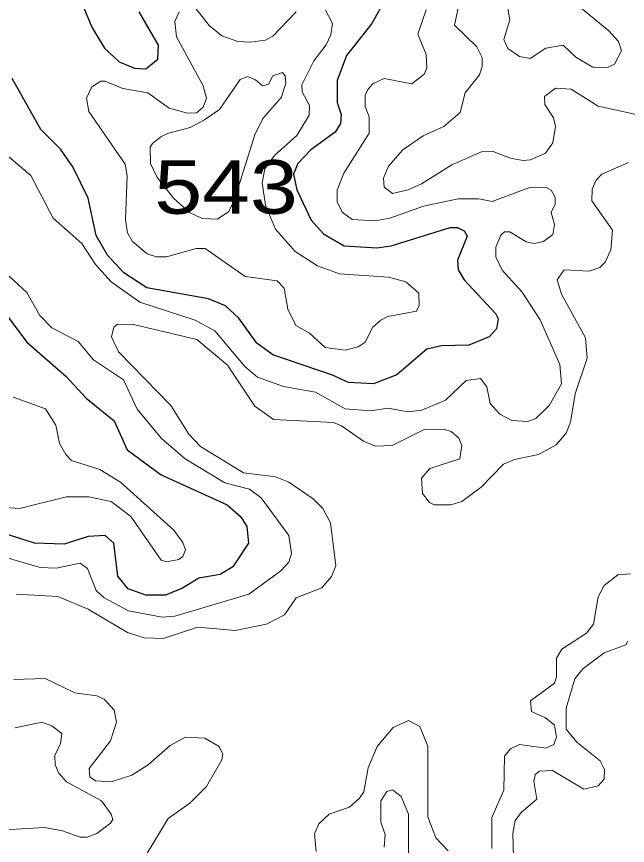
# Model space of a CAD drawing. Extents: x 577 to 602.9, y 7483.8 to 7511.6.
# Drawn here: x 585.493 to 586.406, y 7497.028 to 7498.265 of the extents above; entities that cross this region are included whole.
import ezdxf
from ezdxf.enums import TextEntityAlignment as Align

# ---------------------------------------------------------------- set-up
doc = ezdxf.new("R2010")
doc.units = 0
doc.header["$LTSCALE"] = 0.032
doc.layers.add('1', color=7, linetype='Continuous', lineweight=25)
doc.layers.add('2', color=7, linetype='Continuous', lineweight=13)
doc.layers.add('61', color=7, linetype='Continuous')

msp = doc.modelspace()

# ---------------------------------------------------------------- linework, layer by layer
at = {"layer": '1'}
for points in [[(585.5778, 7498.3164), (585.6057, 7498.2488), (585.6247, 7498.2178), (585.6462, 7498.1971), (585.6693, 7498.1876), (585.686, 7498.1868), (585.7043, 7498.2011), (585.705, 7498.2218), (585.6764, 7498.2719)], [(586.0509, 7498.3029), (586.0239, 7498.2544), (585.9857, 7498.2067), (585.9722, 7498.1693), (585.9722, 7498.1367), (585.9778, 7498.1184), (585.977, 7498.1049), (585.969, 7498.0921), (585.9325, 7498.0659), (585.9134, 7498.0452), (585.907, 7498.0293), (585.9118, 7498.0063), (585.9333, 7497.9609), (585.9516, 7497.9403), (585.9826, 7497.9228), (586.0311, 7497.9196), (586.0525, 7497.9228), (586.1408, 7497.9498), (586.1519, 7497.9498), (586.1615, 7497.945), (586.1662, 7497.9371), (586.1519, 7497.9013), (586.1527, 7497.887), (586.1615, 7497.8719)], [(586.1615, 7497.8719), (586.2084, 7497.8218), (586.2124, 7497.8138), (586.21, 7497.7987), (586.1989, 7497.7868), (586.1686, 7497.7741), (586.1281, 7497.7733), (586.1058, 7497.7685), (586.0613, 7497.7303), (586.0263, 7497.7168), (585.9889, 7497.7184), (585.9651, 7497.7295), (585.876, 7497.7598), (585.8522, 7497.7773), (585.8251, 7497.8146), (585.8052, 7497.8329), (585.7798, 7497.8433), (585.6876, 7497.86), (585.6534, 7497.8822), (585.6287, 7497.9085), (585.612, 7497.9379), (585.6001, 7497.9935), (585.577, 7498.0405), (585.5587, 7498.0667), (585.5293, 7498.0961), (585.4864, 7498.1725)], [(585.4673, 7497.8337), (585.5086, 7497.7788), (585.5667, 7497.728), (585.5969, 7497.6954), (585.639, 7497.6612), (585.6581, 7497.6182), (585.709, 7497.5808), (585.8076, 7497.5363), (585.8283, 7497.518), (585.837, 7497.5037), (585.8394, 7497.4791), (585.8164, 7497.4433), (585.7973, 7497.4321), (585.7655, 7497.4266), (585.7408, 7497.4115), (585.7154, 7497.4011), (585.686, 7497.4011), (585.6597, 7497.4107), (585.6446, 7497.4298), (585.6383, 7497.4791), (585.6255, 7497.4902), (585.6001, 7497.4886), (585.5643, 7497.4775), (585.5198, 7497.4791), (585.4585, 7497.4981)]]:
    msp.add_lwpolyline(points, dxfattribs=at)
at = {"layer": '2'}
for points in [[(585.9547, 7498.2742), (585.9651, 7498.2544), (585.9627, 7498.2377), (585.9555, 7498.2226), (585.9372, 7498.1987), (585.919, 7498.1629), (585.9197, 7498.1526), (585.9309, 7498.1319), (585.9301, 7498.1176), (585.9118, 7498.0874), (585.8784, 7498.0572), (585.8641, 7498.0373), (585.8601, 7498.0166), (585.8649, 7497.9832), (585.88, 7497.9474), (585.9094, 7497.914), (585.9428, 7497.8926), (585.9754, 7497.8806), (586.0486, 7497.8759), (586.0748, 7497.8687), (586.0939, 7497.852), (586.0947, 7497.8337), (586.0907, 7497.825), (586.0478, 7497.817), (586.0374, 7497.8114), (586.0255, 7497.8011), (586.0136, 7497.7788), (586.0032, 7497.7717), (585.9842, 7497.7669), (585.9539, 7497.7709), (585.9309, 7497.7924), (585.9102, 7497.8035), (585.8983, 7497.8281), (585.8927, 7497.8592), (585.8824, 7497.8703), (585.8347, 7497.8767), (585.775, 7497.9188), (585.7615, 7497.9188), (585.717, 7497.9061), (585.7019, 7497.9061), (585.6883, 7497.9108), (585.6661, 7497.9291), (585.6589, 7497.9419), (585.6557, 7497.9617), (585.6581, 7498.0269), (585.6553, 7498.0444), (585.6009, 7498.1232), (585.5977, 7498.143), (585.6057, 7498.1597), (585.6192, 7498.1685), (585.6255, 7498.1685), (585.6518, 7498.1574), (585.6891, 7498.151), (585.721, 7498.1279), (585.7485, 7498.1206), (585.7618, 7498.1211), (585.7718, 7498.1295), (585.7766, 7498.143), (585.7718, 7498.1613), (585.7321, 7498.2345), (585.7297, 7498.2575), (585.7361, 7498.2719)], [(585.7607, 7498.2766), (585.7806, 7498.2512), (585.7997, 7498.2361), (585.8235, 7498.2273), (585.8426, 7498.2265), (585.8649, 7498.2297), (585.876, 7498.2353), (585.911, 7498.2719)], [(586.105, 7498.275), (586.0923, 7498.2385), (586.105, 7498.2082), (586.1058, 7498.1876), (586.1018, 7498.1788), (586.0836, 7498.1645), (586.0422, 7498.1725), (586.0255, 7498.1645), (586.0176, 7498.1558), (586.0136, 7498.147), (586.0136, 7498.1303), (586.0199, 7498.1152), (586.0199, 7498.0906), (585.9818, 7498.0309), (585.9722, 7498.0055), (585.9722, 7497.988)], [(586.4167, 7498.1192), (586.3619, 7498.1311), (586.3213, 7498.1566), (586.2982, 7498.1581), (586.2816, 7498.1454), (586.2823, 7498.1335), (586.2951, 7498.1136), (586.2982, 7498.1009), (586.2943, 7498.0762), (586.2831, 7498.0611), (586.2609, 7498.0508), (586.2497, 7498.05), (586.2307, 7498.0532), (586.2052, 7498.0635), (586.1877, 7498.0627), (586.1432, 7498.0436), (586.0979, 7498.015), (586.078, 7498.0063), (586.0549, 7498.0007), (586.0422, 7498.0102), (586.0414, 7498.0238), (586.0486, 7498.0413), (586.07, 7498.0659), (586.1003, 7498.0866), (586.1313, 7498.1009), (586.1559, 7498.1216), (586.1631, 7498.151), (586.1845, 7498.178), (586.1885, 7498.19), (586.1885, 7498.2035), (586.1806, 7498.2194), (586.1472, 7498.252), (586.1527, 7498.2774)], [(586.2267, 7498.2766), (586.2299, 7498.2599), (586.2211, 7498.2305), (586.2267, 7498.217), (586.2442, 7498.2051), (586.2601, 7498.2019), (586.2839, 7498.2178), (586.3094, 7498.2218), (586.3285, 7498.2043), (586.3539, 7498.1892), (586.3746, 7498.1884), (586.3865, 7498.1939), (586.3969, 7498.2138), (586.3921, 7498.2273), (586.3778, 7498.2432), (586.3277, 7498.2846)], [(585.9722, 7497.988), (585.9794, 7497.9729), (585.9945, 7497.9617), (586.0287, 7497.9601), (586.0509, 7497.9641), (586.101, 7497.9816), (586.1527, 7497.9927), (586.1837, 7497.9927), (586.2036, 7497.9888), (586.2609, 7498.0102), (586.2847, 7498.0094), (586.2919, 7498.0055), (586.2975, 7497.9951), (586.2975, 7497.9848), (586.2919, 7497.9721), (586.2967, 7497.9546), (586.2943, 7497.9395), (586.28, 7497.9291), (586.2664, 7497.926), (586.2545, 7497.9283), (586.2299, 7497.9434), (586.2219, 7497.9434), (586.2163, 7497.9387), (586.2092, 7497.9204), (586.2092, 7497.9061), (586.2187, 7497.8862), (586.2482, 7497.8536), (586.2752, 7497.8122), (586.3046, 7497.7454), (586.307, 7497.7168), (586.2887, 7497.6842), (586.2688, 7497.6651), (586.2561, 7497.6604), (586.233, 7497.662), (586.2148, 7497.6715), (586.2004, 7497.6874), (586.1957, 7497.7121), (586.1861, 7497.7248), (586.1647, 7497.7216), (586.1336, 7497.6922), (586.0987, 7497.6771), (586.078, 7497.6747), (586.0478, 7497.6802), (586.0223, 7497.6763), (585.9842, 7497.6794), (585.9396, 7497.7041), (585.8919, 7497.7128), (585.853, 7497.7264), (585.8339, 7497.7423), (585.7893, 7497.7955), (585.7599, 7497.8114), (585.6772, 7497.8385), (585.6343, 7497.8687), (585.6112, 7497.8949), (585.5905, 7497.926), (585.5476, 7497.9641), (585.5142, 7498.0277), (585.4609, 7498.0723)], [(586.1106, 7497.5904), (586.0979, 7497.5761), (586.0995, 7497.553), (586.1098, 7497.5395), (586.1169, 7497.5363), (586.1416, 7497.5363), (586.1583, 7497.5411), (586.1869, 7497.5626), (586.2203, 7497.5968), (586.237, 7497.6039), (586.2728, 7497.6111), (586.299, 7497.6254), (586.3142, 7497.6429), (586.3205, 7497.6596), (586.3277, 7497.7017), (586.3452, 7497.755), (586.3428, 7497.7852), (586.307, 7497.8504), (586.3006, 7497.8719), (586.311, 7497.887), (586.3483, 7497.8846), (586.3642, 7497.8902), (586.3722, 7497.8981), (586.3809, 7497.9164), (586.3833, 7497.9458), (586.3523, 7497.9896), (586.3531, 7498.0071), (586.3587, 7498.0206), (586.3674, 7498.0293), (586.4072, 7498.0468)], [(585.4768, 7497.8822), (585.5086, 7497.8528), (585.5277, 7497.8186), (585.546, 7497.8003), (585.585, 7497.7796), (585.608, 7497.7526), (585.6526, 7497.7224), (585.6732, 7497.6787), (585.7098, 7497.6349), (585.7448, 7497.6047), (585.8044, 7497.5689), (585.841, 7497.5594), (585.8585, 7497.5467), (585.8999, 7497.4902), (585.9038, 7497.4632), (585.8999, 7497.4504), (585.8879, 7497.4377), (585.8402, 7497.4027), (585.7297, 7497.3701), (585.7106, 7497.3685), (585.6605, 7497.3781), (585.6239, 7497.3972), (585.612, 7497.4083), (585.5993, 7497.4409), (585.5882, 7497.4488), (585.5524, 7497.4417), (585.5285, 7497.4425), (585.4792, 7497.4568)], [(585.4927, 7497.4027), (585.5548, 7497.3995), (585.6001, 7497.3805), (585.6589, 7497.3455), (585.6836, 7497.3375), (585.7122, 7497.3367), (585.7639, 7497.3534), (585.8196, 7497.3487), (585.8665, 7497.3582), (585.8935, 7497.3717), (585.911, 7497.3972), (585.9492, 7497.4123), (585.9635, 7497.429), (585.9698, 7497.4449), (585.9619, 7497.5093), (585.9508, 7497.5308), (585.9364, 7497.5451), (585.8999, 7497.5697), (585.88, 7497.5777), (585.8323, 7497.584), (585.7679, 7497.623), (585.7504, 7497.6413), (585.7233, 7497.6842), (585.6454, 7497.7645), (585.6351, 7497.7868), (585.6383, 7497.8011), (585.6438, 7497.8059), (585.6677, 7497.8051), (585.7623, 7497.7828), (585.8084, 7497.7447), (585.849, 7497.6834), (585.8768, 7497.6635), (585.9667, 7497.6588), (585.9786, 7497.654), (586.0112, 7497.6309), (586.0295, 7497.6238), (586.0541, 7497.6246), (586.1018, 7497.6484), (586.1313, 7497.6492), (586.1424, 7497.6453), (586.1535, 7497.6357), (586.1583, 7497.6246), (586.1551, 7497.6047), (586.1106, 7497.5904)], [(585.488, 7497.6969), (585.5365, 7497.6794), (585.5516, 7497.6548), (585.5571, 7497.6278), (585.5667, 7497.6111), (585.5754, 7497.6023), (585.6176, 7497.5888), (585.6486, 7497.5697), (585.7281, 7497.4981), (585.7416, 7497.4799), (585.7456, 7497.4687), (585.7416, 7497.4592), (585.7353, 7497.4544), (585.7178, 7497.4512), (585.709, 7497.4536), (585.6637, 7497.5188), (585.6343, 7497.5411), (585.6009, 7497.5482), (585.5675, 7497.5482), (585.4975, 7497.5308), (585.476, 7497.5323)], [(586.4104, 7497.4329), (586.3913, 7497.4314)], [(586.3913, 7497.4314), (586.3706, 7497.4155), (586.3619, 7497.3988), (586.3547, 7497.3582), (586.3444, 7497.3447), (586.3078, 7497.3208), (586.2998, 7497.3073), (586.2998, 7497.2795), (586.2967, 7497.2699), (586.2609, 7497.2437), (586.2625, 7497.2278), (586.2831, 7497.2182), (586.2967, 7497.2071), (586.2998, 7497.1896), (586.2959, 7497.1785), (586.2839, 7497.1729), (586.2442, 7497.1785), (586.2307, 7497.1721), (586.2219, 7497.161), (586.2211, 7497.1101), (586.2028, 7497.0695), (586.2028, 7497.0234)], [(586.2354, 7497.0107), (586.2346, 7497.0457), (586.2378, 7497.0648), (586.2474, 7497.0775), (586.2704, 7497.0966), (586.2656, 7497.1236), (586.268, 7497.1332), (586.2736, 7497.1387), (586.2935, 7497.1395), (586.3404, 7497.1117), (586.3619, 7497.1165), (586.3706, 7497.1268), (586.3714, 7497.1411), (586.365, 7497.1538), (586.3301, 7497.1817), (586.3142, 7497.2015), (586.3142, 7497.2326), (586.3269, 7497.2763), (586.3388, 7497.2914), (586.3706, 7497.3153), (586.4032, 7497.3272)], [(586.4032, 7497.3272), (586.4064, 7497.3328)], [(585.639, 7497.2294), (585.6239, 7497.2461), (585.6128, 7497.2508), (585.5802, 7497.2556), (585.5357, 7497.2771), (585.4888, 7497.2755)], [(585.6868, 7497.0139), (585.7194, 7497.068), (585.752, 7497.091), (585.7766, 7497.1157), (585.7997, 7497.1554), (585.8013, 7497.1642), (585.7957, 7497.1753), (585.7742, 7497.188), (585.7456, 7497.1896), (585.7225, 7497.1769), (585.6899, 7497.1483), (585.6653, 7497.1324), (585.6343, 7497.1228), (585.6112, 7497.1244), (585.6025, 7497.13), (585.6017, 7497.1427), (585.6335, 7497.1841), (585.6422, 7497.2119), (585.639, 7497.2294)], [(585.4911, 7497.2031), (585.5309, 7497.2119), (585.546, 7497.2063), (585.5608, 7497.195), (585.5586, 7497.1801), (585.5501, 7497.162), (585.5508, 7497.1483), (585.5563, 7497.1355), (585.5675, 7497.1228), (585.62, 7497.0942), (585.6343, 7497.0743), (585.6367, 7497.0664), (585.6335, 7497.0608), (585.6128, 7497.0457), (585.5985, 7497.0401), (585.5882, 7497.0401), (585.5619, 7497.0497), (585.5349, 7497.0544), (585.4498, 7497.0497)], [(586.1376, 7497.0195), (586.1193, 7497.0393), (586.1074, 7497.0703), (586.1074, 7497.1761), (586.0955, 7497.2055), (586.0788, 7497.2143), (586.0557, 7497.2039), (586.0319, 7497.1753), (586.0183, 7497.1435), (586.012, 7497.1077), (586.0056, 7497.0982), (585.9905, 7497.0847), (585.9603, 7497.0743), (585.9444, 7497.06), (585.938, 7497.0449), (585.9405, 7497.0186)], [(586.0422, 7497.025), (586.0438, 7497.0441), (586.0374, 7497.0624), (586.0374, 7497.0942), (586.0462, 7497.1085), (586.0549, 7497.1109), (586.0676, 7497.1006), (586.0788, 7497.0743), (586.0788, 7497.0083)]]:
    msp.add_lwpolyline(points, dxfattribs=at)
msp.add_lwpolyline([(585.7087, 7498.085), (585.7184, 7498.0903), (585.7522, 7498.0993), (585.7739, 7498.1107), (585.7964, 7498.1262), (585.8269, 7498.1708), (585.8379, 7498.1752), (585.85, 7498.1703), (585.8605, 7498.1614), (585.8693, 7498.1636), (585.876, 7498.1764), (585.8903, 7498.1812), (585.8943, 7498.1764), (585.8951, 7498.1653), (585.8887, 7498.1446), (585.8609, 7498.1128), (585.849, 7498.0882), (585.818, 7497.9904), (585.81, 7497.9737), (585.7933, 7497.9625), (585.7703, 7497.9633), (585.7512, 7497.9721), (585.7273, 7497.9935), (585.7027, 7498.0254), (585.6931, 7498.0452), (585.6927, 7498.0696), (585.6963, 7498.0753)], close=True, dxfattribs=at)

# ---------------------------------------------------------------- texts
at = {"layer": '61', "width": 1.2}
msp.add_text('543', height=0.08, dxfattribs=at).set_placement((585.8061, 7497.9704), align=Align.CENTER)

doc.saveas('drawing.dxf')
